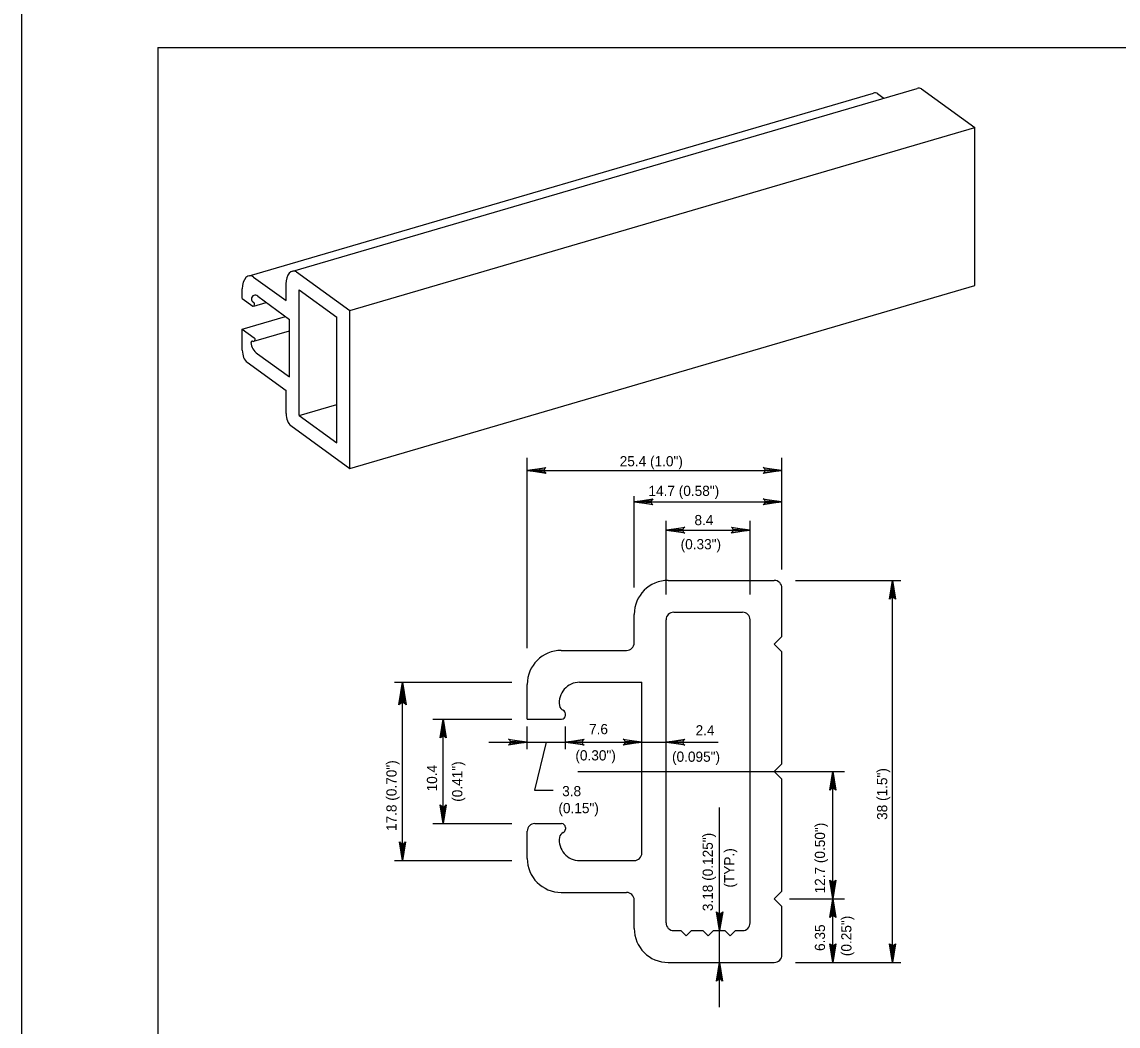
# Model space of a CAD drawing. Extents: x 650495 to 652241, y 298458 to 299646.
# Drawn here: x 650495.3 to 650818, y 298748.5 to 299044.1 of the extents above; entities that cross this region are included whole.
import ezdxf

# ---------------------------------------------------------------- set-up
doc = ezdxf.new("R2010")
doc.units = 0
for name, color, linetype in [('1', 7, 'Continuous'), ('2', 7, 'Continuous'), ('PLT-BNDY', 7, 'Continuous')]:
    doc.layers.add(name, color=color, linetype=linetype)

msp = doc.modelspace()

# ---------------------------------------------------------------- linework, layer by layer
at = {"layer": '1'}
for q in [(651321.31, 299036.63), (650535.31, 298472.63)]:
    msp.add_line((650535.31, 299036.63), q, dxfattribs=at)
at = {"layer": '2'}
for p, q in [((650575.03, 298970.77), (650758.88, 299024.56)), ((650562.19, 298969.37), (650745.99, 299023.15)), ((650747.31, 299022.97), (650749.08, 299021.69)), ((650760.18, 299024.39), (650775.84, 299013.04)), ((650591.84, 298959.2), (650775.84, 299013.04)), ((650775.84, 298966.51), (650775.84, 299013.04)), ((650576.15, 298970.57), (650591.84, 298959.2)), ((650563.48, 298969.01), (650573.07, 298962.06)), ((650573.07, 298962.06), (650573.07, 298966.98)), ((650591.84, 298912.67), (650775.84, 298966.51)), ((650560.2, 298962.65), (650560.2, 298965.56)), ((650564.72, 298963.36), (650574.13, 298956.54)), ((650576.91, 298965.26), (650587.99, 298957.23)), ((650576.91, 298928.24), (650576.91, 298965.26)), ((650560.2, 298962.65), (650563.3, 298960.4)), ((650563.55, 298960.46), (650567.23, 298961.54)), ((650563.82, 298960.92), (650563.82, 298961.14)), ((650560.2, 298953.67), (650572.94, 298957.4)), ((650587.99, 298920.21), (650587.99, 298957.23)), ((650591.84, 298912.67), (650591.84, 298959.2)), ((650560.2, 298953.67), (650563.71, 298951.12)), ((650560.2, 298947.48), (650560.2, 298953.67)), ((650574.13, 298939.59), (650574.13, 298956.54)), ((650563.63, 298950.14), (650574.13, 298953.21)), ((650561.59, 298943.93), (650573.07, 298935.61)), ((650564.7, 298946.42), (650574.13, 298939.59)), ((650573.07, 298928.83), (650573.07, 298935.61)), ((650576.91, 298928.24), (650587.99, 298931.48)), ((650576.91, 298928.24), (650587.99, 298920.21)), ((650574.45, 298925.27), (650591.84, 298912.67)), ((650644.08, 298859.79), (650644.08, 298915.76)), ((650719.07, 298882.92), (650719.07, 298915.76)), ((650644.08, 298912.08), (650719.07, 298912.08)), ((650675.58, 298877.58), (650675.58, 298904.5)), ((650675.58, 298902.83), (650719.07, 298902.83)), ((650684.95, 298875.52), (650684.95, 298897.26)), ((650709.7, 298875.52), (650709.7, 298897.26)), ((650684.95, 298894.5), (650709.7, 298894.5)), ((650685.58, 298879.7), (650716.82, 298879.7)), ((650723.11, 298879.7), (650754.1, 298879.7)), ((650751.61, 298767.21), (650751.61, 298879.7)), ((650719.07, 298863.2), (650719.07, 298877.45)), ((650675.58, 298861.33), (650675.58, 298869.7)), ((650687.2, 298870.33), (650707.45, 298870.33)), ((650684.95, 298778.83), (650684.95, 298868.08)), ((650709.7, 298778.83), (650709.7, 298868.08)), ((650716.82, 298860.95), (650719.07, 298863.2)), ((650716.82, 298860.95), (650719.07, 298858.7)), ((650654.08, 298859.08), (650673.33, 298859.08)), ((650719.07, 298825.7), (650719.07, 298858.7)), ((650604.97, 298849.7), (650639.52, 298849.7)), ((650607.34, 298797.2), (650607.34, 298849.7)), ((650644.08, 298838.83), (650644.08, 298849.08)), ((650659.5, 298849.7), (650677.83, 298849.7)), ((650677.83, 298799.45), (650677.83, 298849.7)), ((650616.3, 298838.83), (650639.52, 298838.83)), ((650619.37, 298808.08), (650619.37, 298838.83)), ((650644.08, 298838.83), (650654.21, 298838.83)), ((650655.33, 298839.95), (650655.33, 298840.43)), ((650644.08, 298830), (650644.08, 298836.71)), ((650655.33, 298830), (650655.33, 298836.71)), ((650632.82, 298832.06), (650644.08, 298832.06)), ((650644.08, 298832.06), (650655.33, 298832.06)), ((650649.7, 298832.06), (650646.18, 298817.91)), ((650655.33, 298832.06), (650677.83, 298832.06)), ((650677.83, 298832.06), (650684.95, 298832.06)), ((650684.95, 298832.06), (650700.33, 298832.06)), ((650716.82, 298823.45), (650719.07, 298825.7)), ((650658.95, 298823.45), (650737.45, 298823.45)), ((650716.82, 298823.45), (650719.07, 298821.2)), ((650719.07, 298788.2), (650719.07, 298821.2)), ((650730.98, 298823.45), (650737.45, 298823.45)), ((650734.04, 298785.95), (650734.04, 298823.45)), ((650646.18, 298817.91), (650651.74, 298817.91)), ((650700.73, 298776.58), (650700.73, 298812.84)), ((650616.3, 298808.08), (650639.52, 298808.08)), ((650644.08, 298797.83), (650644.08, 298805.83)), ((650646.33, 298808.08), (650654.21, 298808.08)), ((650655.33, 298806.95), (650655.33, 298806.48)), ((650604.97, 298797.2), (650639.52, 298797.2)), ((650659.5, 298797.2), (650675.58, 298797.2)), ((650654.08, 298787.83), (650673.33, 298787.83)), ((650716.82, 298785.95), (650719.07, 298788.2)), ((650716.82, 298785.95), (650719.07, 298783.7)), ((650721.26, 298785.95), (650737.45, 298785.95)), ((650734.04, 298767.21), (650734.04, 298785.95)), ((650675.58, 298777.21), (650675.58, 298785.58)), ((650719.07, 298769.46), (650719.07, 298783.7)), ((650687.2, 298776.58), (650689.28, 298776.58)), ((650690.84, 298775.02), (650689.28, 298776.58)), ((650690.84, 298775.02), (650692.41, 298776.58)), ((650692.41, 298776.58), (650695.76, 298776.58)), ((650697.32, 298775.02), (650695.76, 298776.58)), ((650697.32, 298775.02), (650698.89, 298776.58)), ((650698.89, 298776.58), (650702.24, 298776.58)), ((650700.73, 298767.21), (650700.73, 298776.58)), ((650703.81, 298775.02), (650702.24, 298776.58)), ((650703.81, 298775.02), (650705.37, 298776.58)), ((650705.37, 298776.58), (650707.45, 298776.58)), ((650685.58, 298767.21), (650716.82, 298767.21)), ((650700.73, 298754.04), (650700.73, 298767.21)), ((650723.11, 298767.21), (650754.1, 298767.21))]:
    msp.add_line(p, q, dxfattribs=at)
for points in [[(650649.33, 298911.42), (650649.14, 298911.8), (650644.08, 298912.08), (650649.33, 298911.42), (650649.6, 298911.19), (650644.08, 298912.08), (650649.13, 298912.33), (650649.32, 298912.71), (650644.08, 298912.08), (650649.6, 298912.96), (650649.32, 298912.71)], [(650713.82, 298912.74), (650714.01, 298912.36), (650719.07, 298912.08), (650713.82, 298912.74), (650713.55, 298912.97), (650719.07, 298912.08), (650714.02, 298911.83), (650713.83, 298911.45), (650719.07, 298912.08), (650713.55, 298911.2), (650713.83, 298911.45)], [(650680.83, 298902.17), (650680.63, 298902.55), (650675.58, 298902.83), (650680.83, 298902.17), (650681.1, 298901.94), (650675.58, 298902.83), (650680.63, 298903.08), (650680.82, 298903.46), (650675.58, 298902.83), (650681.1, 298903.71), (650680.82, 298903.46)], [(650713.82, 298903.49), (650714.01, 298903.11), (650719.07, 298902.83), (650713.82, 298903.49), (650713.55, 298903.72), (650719.07, 298902.83), (650714.02, 298902.58), (650713.83, 298902.2), (650719.07, 298902.83), (650713.55, 298901.95), (650713.83, 298902.2)], [(650690.21, 298893.84), (650690.01, 298894.22), (650684.95, 298894.5), (650690.21, 298893.84), (650690.47, 298893.61), (650684.95, 298894.5), (650690.01, 298894.75), (650690.19, 298895.13), (650684.95, 298894.5), (650690.47, 298895.38), (650690.19, 298895.13)], [(650704.44, 298895.16), (650704.64, 298894.78), (650709.7, 298894.5), (650704.44, 298895.16), (650704.18, 298895.39), (650709.7, 298894.5), (650704.64, 298894.25), (650704.46, 298893.88), (650709.7, 298894.5), (650704.18, 298893.63), (650704.46, 298893.88)], [(650750.95, 298874.45), (650751.34, 298874.64), (650751.61, 298879.7), (650750.95, 298874.45), (650750.72, 298874.18), (650751.61, 298879.7), (650751.86, 298874.65), (650752.24, 298874.46), (650751.61, 298879.7), (650752.49, 298874.18), (650752.24, 298874.46)], [(650606.55, 298843.4), (650607.01, 298843.63), (650607.34, 298849.7), (650606.55, 298843.4), (650606.27, 298843.07), (650607.34, 298849.7), (650607.64, 298843.64), (650608.09, 298843.41), (650607.34, 298849.7), (650608.39, 298843.07), (650608.09, 298843.41)], [(650606.55, 298843.4), (650607.01, 298843.63), (650607.34, 298849.7), (650606.55, 298843.4), (650606.27, 298843.07), (650607.34, 298849.7), (650607.64, 298843.64), (650608.09, 298843.41), (650607.34, 298849.7), (650608.39, 298843.07), (650608.09, 298843.41)], [(650618.71, 298833.57), (650619.09, 298833.77), (650619.37, 298838.83), (650618.71, 298833.57), (650618.48, 298833.3), (650619.37, 298838.83), (650619.62, 298833.77), (650619.99, 298833.59), (650619.37, 298838.83), (650620.24, 298833.3), (650619.99, 298833.59)], [(650638.82, 298832.72), (650639.02, 298832.34), (650644.08, 298832.06), (650638.82, 298832.72), (650638.55, 298832.95), (650644.08, 298832.06), (650639.02, 298831.81), (650638.84, 298831.43), (650644.08, 298832.06), (650638.55, 298831.18), (650638.84, 298831.43)], [(650660.59, 298831.4), (650660.39, 298831.78), (650655.33, 298832.06), (650660.59, 298831.4), (650660.86, 298831.17), (650655.33, 298832.06), (650660.39, 298832.31), (650660.57, 298832.68), (650655.33, 298832.06), (650660.86, 298832.93), (650660.57, 298832.68)], [(650672.58, 298832.72), (650672.77, 298832.34), (650677.83, 298832.06), (650672.58, 298832.72), (650672.31, 298832.95), (650677.83, 298832.06), (650672.78, 298831.81), (650672.59, 298831.43), (650677.83, 298832.06), (650672.31, 298831.18), (650672.59, 298831.43)], [(650690.21, 298831.4), (650690.01, 298831.78), (650684.95, 298832.06), (650690.21, 298831.4), (650690.47, 298831.17), (650684.95, 298832.06), (650690.01, 298832.31), (650690.19, 298832.68), (650684.95, 298832.06), (650690.47, 298832.93), (650690.19, 298832.68)], [(650733.38, 298818.2), (650733.76, 298818.39), (650734.04, 298823.45), (650733.38, 298818.2), (650733.15, 298817.93), (650734.04, 298823.45), (650734.29, 298818.4), (650734.66, 298818.21), (650734.04, 298823.45), (650734.91, 298817.93), (650734.66, 298818.21)], [(650620.03, 298813.33), (650619.65, 298813.14), (650619.37, 298808.08), (650620.03, 298813.33), (650620.26, 298813.6), (650619.37, 298808.08), (650619.12, 298813.13), (650618.74, 298813.32), (650619.37, 298808.08), (650618.49, 298813.6), (650618.74, 298813.32)], [(650608, 298802.46), (650607.62, 298802.26), (650607.34, 298797.2), (650608, 298802.46), (650608.23, 298802.73), (650607.34, 298797.2), (650607.09, 298802.26), (650606.71, 298802.44), (650607.34, 298797.2), (650606.46, 298802.73), (650606.71, 298802.44)], [(650734.7, 298791.21), (650734.32, 298791.01), (650734.04, 298785.95), (650734.7, 298791.21), (650734.93, 298791.48), (650734.04, 298785.95), (650733.79, 298791.01), (650733.41, 298791.19), (650734.04, 298785.95), (650733.16, 298791.48), (650733.41, 298791.19)], [(650733.38, 298780.7), (650733.76, 298780.9), (650734.04, 298785.95), (650733.38, 298780.7), (650733.15, 298780.43), (650734.04, 298785.95), (650734.29, 298780.9), (650734.66, 298780.72), (650734.04, 298785.95), (650734.91, 298780.43), (650734.66, 298780.72)], [(650701.39, 298781.83), (650701.01, 298781.64), (650700.73, 298776.58), (650701.39, 298781.83), (650701.62, 298782.1), (650700.73, 298776.58), (650700.48, 298781.64), (650700.11, 298781.82), (650700.73, 298776.58), (650699.85, 298782.1), (650700.11, 298781.82)], [(650734.7, 298772.46), (650734.32, 298772.26), (650734.04, 298767.21), (650734.7, 298772.46), (650734.93, 298772.73), (650734.04, 298767.21), (650733.79, 298772.26), (650733.41, 298772.45), (650734.04, 298767.21), (650733.16, 298772.73), (650733.41, 298772.45)], [(650752.27, 298772.46), (650751.89, 298772.26), (650751.61, 298767.21), (650752.27, 298772.46), (650752.5, 298772.73), (650751.61, 298767.21), (650751.36, 298772.26), (650750.99, 298772.45), (650751.61, 298767.21), (650750.74, 298772.73), (650750.99, 298772.45)], [(650700.07, 298761.95), (650700.45, 298762.15), (650700.73, 298767.21), (650700.07, 298761.95), (650699.84, 298761.68), (650700.73, 298767.21), (650700.98, 298762.15), (650701.36, 298761.97), (650700.73, 298767.21), (650701.61, 298761.68), (650701.36, 298761.97)]]:
    msp.add_lwpolyline(points, dxfattribs=at)
for centre, radius, start, end in [((650563.95, 298962.6), 1.08, 44.621, 246.0481), ((650563.3, 298960.92), 0.52, 270, 0), ((650563.3, 298961.14), 0.52, 0, 66.0481), ((650563.38, 298950.65), 0.571, 250.8042, 54.059), ((650563.09, 298949.8), 0.333, 70.8042, 182.3162), ((650566.88, 298949.94), 4.13, 182.245, 238.3169), ((650685.58, 298869.7), 10, 90, 180), ((650716.82, 298877.45), 2.25, 0, 90), ((650687.2, 298868.08), 2.25, 90, 180), ((650707.45, 298868.08), 2.25, 0, 90), ((650673.33, 298861.33), 2.25, 270, 0), ((650654.08, 298849.08), 10, 90, 180), ((650659.5, 298843.7), 6, 90, 188.0391), ((650655.44, 298843.2), 1.91, 190.1449, 246.0481), ((650654.21, 298840.43), 1.12, 0, 66.0481), ((650654.21, 298839.95), 1.12, 270, 0), ((650646.33, 298805.83), 2.25, 90, 180), ((650655.44, 298803.71), 1.91, 113.9519, 169.8551), ((650654.21, 298806.95), 1.12, 0, 90), ((650654.21, 298806.48), 1.12, 293.9519, 360), ((650659.5, 298803.2), 6, 171.9609, 270), ((650675.58, 298799.45), 2.25, 270, 0), ((650654.08, 298797.83), 10, 180, 270), ((650673.33, 298785.58), 2.25, 0, 90), ((650685.58, 298777.21), 10, 180, 270), ((650687.2, 298778.83), 2.25, 180, 270), ((650707.45, 298778.83), 2.25, 270, 360), ((650716.82, 298769.46), 2.25, 270, 360)]:
    msp.add_arc(centre, radius, start, end, dxfattribs=at)
for centre, major_axis, start_param, end_param in [((650759.52, 299020.44), (0.26, -4.2), 2.759334, 3.301342), ((650746.64, 299019.03), (0.26, -4.2), 2.759334, 3.301342), ((650562.63, 298965.2), (0.26, -4.2), 2.674345, 4.589197), ((650575.49, 298966.61), (0.26, -4.2), 2.759334, 4.589197), ((650562.63, 298947.85), (0.26, 4.2), 1.693988, 2.807682), ((650575.5, 298929.19), (0.26, 4.2), 1.693988, 2.807682)]:
    msp.add_ellipse(centre, major_axis=major_axis, ratio=0.576402, start_param=start_param, end_param=end_param, dxfattribs=at)
at = {"layer": 'PLT-BNDY'}
msp.add_lwpolyline([(650495.31, 299051.63), (651336.31, 299051.63), (651336.31, 298457.63), (650495.31, 298457.63)], close=True, dxfattribs=at)

# ---------------------------------------------------------------- texts
at = {"layer": '2'}
for s, height, p in [('25.4 (1.0")', 2.9999, (650671.31, 298913.28)), ('14.7 (0.58")', 3, (650679.77, 298904.56)), ('8.4', 3, (650693.32, 298895.96)), ('(0.33")', 3, (650689.24, 298888.86)), ('7.6', 3, (650662.28, 298834.41)), ('2.4', 3, (650693.65, 298834.06)), ('(0.30")', 3, (650658.26, 298826.69)), ('(0.095")', 3, (650686.71, 298826.29)), ('3.8', 3, (650654.37, 298816.16)), ('(0.15")', 3, (650653.26, 298811.16))]:
    msp.add_text(s, height=height, dxfattribs=at).set_placement(p)
for s, p in [('17.8 (0.70")', (650605.61, 298805.9)), ('10.4', (650617.54, 298817.56)), ('(0.41")', (650624.98, 298814.51)), ('38 (1.5")', (650750.07, 298809.17)), ('3.18 (0.125")', (650698.73, 298782.31)), ('12.7 (0.50")', (650731.76, 298787.52)), ('(TYP.)', (650705.06, 298789.25)), ('(0.25")', (650739.53, 298769.06)), ('6.35', (650731.76, 298770.59))]:
    msp.add_text(s, height=3, rotation=90, dxfattribs=at).set_placement(p)

doc.saveas('drawing.dxf')
